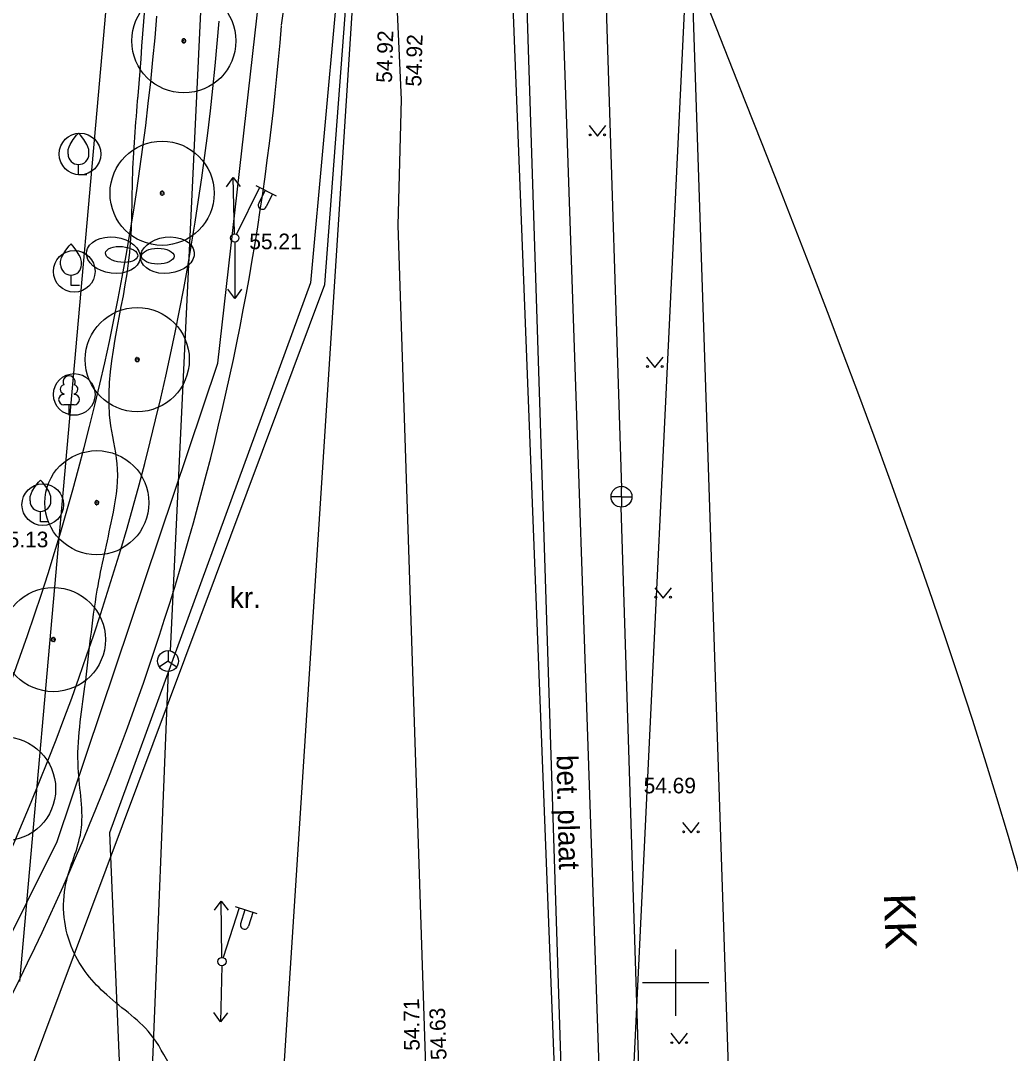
# Model space of a CAD drawing. Extents: x 9156 to 9809, y 2728 to 4000.
# Drawn here: x 9518.57 to 9566.07, y 3596.6 to 3646.17 of the extents above; entities that cross this region are included whole.
import ezdxf

# ---------------------------------------------------------------- set-up
doc = ezdxf.new("R2010")
doc.units = 0
for name, color, linetype in [('Level 1', 7, 'Continuous'), ('Level 16', 7, 'Continuous'), ('Level 17', 7, 'Continuous'), ('Level 18', 7, 'Continuous'), ('Level 21', 7, 'Continuous'), ('Level 54', 7, 'Continuous'), ('Level 56', 7, 'Continuous'), ('Level 58', 7, 'Continuous'), ('Level 7', 7, 'Continuous'), ('Level 8', 7, 'Continuous'), ('Level 9', 7, 'Continuous')]:
    doc.layers.add(name, color=color, linetype=linetype)

# ---------------------------------------------------------------- blocks, each defined once
blk = doc.blocks.new('KKOL')
at = {"layer": 'Level 58'}
for p, q in [((0, 1.59349), (0, -1.5935)), ((-1.5935, 0), (1.59349, 0))]:
    blk.add_line(p, q, dxfattribs=at)

msp = doc.modelspace()

# ---------------------------------------------------------------- linework, layer by layer
at = {"layer": 'Level 1'}
msp.add_line((9552.269, 3685.137), (9546.632, 3567.879), dxfattribs=at)
msp.add_line((9552.269, 3685.137), (9546.632, 3567.879), dxfattribs=at)
at = {"layer": 'Level 16'}
for p, q in [((9528.027, 3629.73), (9530.595, 3652.391)), ((9520.325, 3606.767), (9528.027, 3629.73)), ((9512.774, 3591.659), (9520.325, 3606.767))]:
    msp.add_line(p, q, dxfattribs=at)
at = {"layer": 'Level 17'}
msp.add_line((9531.089, 3645.951), (9534.27, 3668.117), dxfattribs=at)
for radius, start in [(123.6, 323.52136), (126.6, 332.03745)]:
    msp.add_arc((9404.886, 3655.965), radius, start, 355.44602, dxfattribs=at)
at = {"layer": 'Level 18'}
for p, q in [((9533.165, 3633.502), (9535.778, 3667.939)), ((9541.349, 3668.295), (9545.183, 3569.878)), ((9516.875, 3589.923), (9533.165, 3633.502))]:
    msp.add_line(p, q, dxfattribs=at)
msp.add_arc((9404.886, 3655.965), 120.6, 323.52136, 355.44602, dxfattribs=at)
at = {"layer": 'Level 21'}
for centre in [(9521.415, 3639.768), (9521.14, 3634.135), (9521.14, 3628.227), (9519.63, 3622.937)]:
    msp.add_circle(centre, 1, dxfattribs=at)
at = {"layer": 'Level 54'}
for p, q in [((9530.197, 3710.192), (9525.746, 3615.921)), ((9541.865, 3677.837), (9545.509, 3564.357)), ((9518.529, 3600.046), (9524.138, 3663.351)), ((9544.314, 3654.566), (9547.393, 3564.619)), ((9546.465, 3652.931), (9547.404, 3623.728)), ((9536.853, 3642.38), (9536.432, 3651.179)), ((9553.951, 3553.575), (9550.727, 3650.558)), ((9534.55, 3647.996), (9531.162, 3595.485)), ((9524.193, 3642.411), (9524.201, 3642.537)), ((9536.689, 3636.356), (9536.853, 3642.38)), ((9545.847, 3641.134), (9546.25, 3640.629)), ((9546.25, 3640.629), (9546.647, 3641.134)), ((9521.346, 3638.763), (9521.346, 3639.263)), ((9521.746, 3638.763), (9521.346, 3638.763)), ((9528.445, 3638.188), (9528.764, 3638.636)), ((9528.838, 3635.937), (9528.764, 3638.636)), ((9528.764, 3638.636), (9529.107, 3638.207)), ((9529.85, 3638.251), (9530.839, 3637.768)), ((9530.03, 3638.163), (9528.932, 3635.917)), ((9530.3, 3638.031), (9529.992, 3637.402)), ((9530.659, 3637.856), (9530.351, 3637.227)), ((9538.677, 3575.871), (9536.689, 3636.356)), ((9528.844, 3635.538), (9528.844, 3632.838)), ((9520.987, 3633.454), (9520.987, 3633.954)), ((9521.387, 3633.454), (9520.987, 3633.454)), ((9528.844, 3632.838), (9528.513, 3633.277)), ((9529.175, 3633.277), (9528.844, 3632.838)), ((9548.602, 3630.022), (9549.005, 3629.516)), ((9549.005, 3629.516), (9549.402, 3630.022)), ((9520.643, 3628.262), (9520.643, 3628.23)), ((9521.143, 3628.262), (9521.143, 3628.23)), ((9521.143, 3627.73), (9520.643, 3627.73)), ((9520.893, 3627.23), (9520.893, 3627.73)), ((9521.293, 3627.23), (9520.893, 3627.23)), ((9547.404, 3623.318), (9547.404, 3623.818)), ((9547.404, 3623.318), (9546.904, 3623.318)), ((9547.404, 3623.318), (9547.904, 3623.318)), ((9547.404, 3623.318), (9547.404, 3622.818)), ((9547.375, 3622.819), (9548.339, 3592.067)), ((9519.521, 3622.114), (9519.521, 3622.614)), ((9519.921, 3622.114), (9519.521, 3622.114)), ((9549.005, 3618.949), (9549.408, 3618.444)), ((9549.408, 3618.444), (9549.805, 3618.949)), ((9525.642, 3615.932), (9525.642, 3615.432)), ((9525.642, 3615.432), (9525.226, 3615.155)), ((9525.642, 3615.432), (9526.058, 3615.155)), ((9523.034, 3549.934), (9525.663, 3614.932)), ((9550.339, 3607.686), (9550.742, 3607.181)), ((9550.742, 3607.181), (9551.139, 3607.686)), ((9527.869, 3603.467), (9528.194, 3603.91)), ((9528.227, 3601.21), (9528.194, 3603.91)), ((9528.194, 3603.91), (9528.531, 3603.475)), ((9529.049, 3603.583), (9528.29, 3601.201)), ((9528.859, 3603.643), (9529.907, 3603.309)), ((9529.335, 3603.492), (9529.123, 3602.825)), ((9529.716, 3603.37), (9529.504, 3602.703)), ((9550, 3601.25), (9550, 3598.75)), ((9528.225, 3600.81), (9528.16, 3598.111)), ((9548.75, 3600), (9551.25, 3600)), ((9528.16, 3598.111), (9527.84, 3598.558)), ((9528.502, 3598.542), (9528.16, 3598.111)), ((9549.773, 3597.566), (9550.176, 3597.061)), ((9550.176, 3597.061), (9550.573, 3597.566))]:
    msp.add_line(p, q, dxfattribs=at)
for points in [[(9520.846, 3639.763), (9520.846, 3639.913), (9520.856, 3639.979), (9520.893, 3640.107), (9520.949, 3640.23), (9521.096, 3640.463), (9521.256, 3640.668), (9521.346, 3640.763)], [(9521.846, 3639.763), (9521.846, 3639.913), (9521.836, 3639.979), (9521.798, 3640.107), (9521.742, 3640.23), (9521.596, 3640.463), (9521.436, 3640.668), (9521.346, 3640.763)], [(9520.487, 3634.454), (9520.487, 3634.604), (9520.497, 3634.67), (9520.535, 3634.798), (9520.591, 3634.921), (9520.737, 3635.154), (9520.897, 3635.359), (9520.987, 3635.454)], [(9521.487, 3634.454), (9521.487, 3634.604), (9521.477, 3634.67), (9521.44, 3634.798), (9521.384, 3634.921), (9521.237, 3635.154), (9521.077, 3635.359), (9520.987, 3635.454)], [(9519.021, 3623.114), (9519.021, 3623.264), (9519.031, 3623.33), (9519.069, 3623.458), (9519.125, 3623.581), (9519.271, 3623.814), (9519.431, 3624.019), (9519.521, 3624.114)], [(9520.021, 3623.114), (9520.021, 3623.264), (9520.011, 3623.33), (9519.974, 3623.458), (9519.918, 3623.581), (9519.771, 3623.814), (9519.611, 3624.019), (9519.521, 3624.114)]]:
    msp.add_lwpolyline(points, dxfattribs=at)
for centre, radius in [((9545.897, 3640.684), 0.0428), ((9546.597, 3640.684), 0.0452), ((9528.844, 3635.738), 0.2), ((9548.652, 3629.572), 0.0428), ((9549.352, 3629.572), 0.0452), ((9547.404, 3623.318), 0.5), ((9549.055, 3618.499), 0.0428), ((9549.755, 3618.499), 0.0452), ((9525.642, 3615.432), 0.5), ((9550.389, 3607.236), 0.0428), ((9551.089, 3607.236), 0.0452), ((9528.23, 3601.01), 0.2), ((9549.823, 3597.116), 0.0428), ((9550.523, 3597.116), 0.0452)]:
    msp.add_circle(centre, radius, dxfattribs=at)
for centre, radius, start, end in [((9521.346, 3639.763), 0.5, 180, 0), ((9530.172, 3637.314), 0.2, 153.8818, 334.0032), ((9520.987, 3634.454), 0.5, 180, 0), ((9520.893, 3628.83), 0.292, 332.5799, 207.4201), ((9520.693, 3628.48), 0.224, 105.2441, 257.079), ((9521.093, 3628.48), 0.224, 282.921, 74.7559), ((9520.643, 3627.98), 0.25, 90, 270), ((9521.143, 3627.98), 0.25, 270, 90), ((9519.521, 3623.114), 0.5, 180, 0), ((9529.313, 3602.764), 0.2, 162.2685, 342.3899)]:
    msp.add_arc(centre, radius, start, end, dxfattribs=at)
for points in [[(9538.06, 3594.642), (9536.329, 3593.597), (9534.047, 3593.075), (9532.091, 3592.553), (9529.613, 3592.814), (9527.787, 3593.923), (9525.961, 3595.685), (9524.918, 3597.382), (9522.701, 3599.405), (9521.07, 3601.558), (9520.744, 3604.755), (9521.462, 3607.235), (9521.331, 3610.302), (9521.657, 3614.217), (9522.246, 3618.832), (9522.963, 3622.29), (9523.224, 3624.639), (9522.898, 3626.727), (9523.811, 3635.059), (9523.942, 3638.583), (9524.202, 3642.563), (9524.79, 3652.067), (9524.855, 3655.721), (9524.985, 3659.18), (9525.238, 3666.92)], [(9551.163, 3554.03), (9551.63, 3553.617), (9552.412, 3553.356), (9553.456, 3553.552), (9550.134, 3650.407)]]:
    msp.add_spline(points, degree=3, dxfattribs=at)
at = {"layer": 'Level 56'}
for p, q in [((9531.089, 3645.951), (9534.27, 3668.117)), ((9533.165, 3633.502), (9535.778, 3667.939)), ((9541.349, 3668.295), (9545.183, 3569.878)), ((9516.875, 3589.923), (9533.165, 3633.502))]:
    msp.add_line(p, q, dxfattribs=at)
for radius, start in [(120.6, 323.52136), (123.6, 323.52136), (126.6, 332.03745)]:
    msp.add_arc((9404.886, 3655.965), radius, start, 355.44602, dxfattribs=at)
at = {"layer": 'Level 7'}
for p, q in [((9535.382, 3665.696), (9532.485, 3633.588)), ((9532.485, 3633.588), (9522.84, 3607.185)), ((9522.84, 3607.185), (9527.159, 3503.746))]:
    msp.add_line(p, q, dxfattribs=at)
at = {"layer": 'Level 8'}
for centre, major_axis, ratio in [((9523.02, 3634.91), (1.285, -0.15), 0.674652), ((9523.02, 3634.91), (1.285, -0.15), 0.674652), ((9523.02, 3634.91), (1.285, -0.15), 0.674652), ((9523.02, 3634.91), (1.285, -0.15), 0.674652), ((9525.613, 3634.91), (-1.285, -0.15), 0.674652), ((9525.613, 3634.91), (-1.285, -0.15), 0.674652), ((9525.613, 3634.91), (-1.285, -0.15), 0.674652), ((9525.613, 3634.91), (-1.285, -0.15), 0.674652), ((9523.415, 3634.947), (0.774, -0.072), 0.486914), ((9523.415, 3634.947), (0.774, -0.072), 0.486914), ((9523.415, 3634.947), (0.774, -0.072), 0.486914), ((9523.415, 3634.947), (0.774, -0.072), 0.486914), ((9525.153, 3634.866), (-0.778, 0.002), 0.486914), ((9525.153, 3634.866), (-0.778, 0.002), 0.486914), ((9525.153, 3634.866), (-0.778, 0.002), 0.486914), ((9525.153, 3634.866), (-0.778, 0.002), 0.486914)]:
    msp.add_ellipse(centre, major_axis=major_axis, ratio=ratio, dxfattribs=at)
at = {"layer": 'Level 9'}
for p, q in [((9526.323, 3645.212), (9526.302, 3645.215)), ((9526.302, 3645.187), (9526.323, 3645.19)), ((9526.31, 3645.243), (9526.33, 3645.235)), ((9526.33, 3645.168), (9526.31, 3645.158)), ((9526.342, 3645.253), (9526.325, 3645.267)), ((9526.325, 3645.135), (9526.341, 3645.15)), ((9526.347, 3645.285), (9526.358, 3645.267)), ((9526.359, 3645.134), (9526.347, 3645.116)), ((9526.372, 3645.104), (9526.378, 3645.125)), ((9526.38, 3645.277), (9526.373, 3645.297)), ((9526.412, 3645.2), (9526.391, 3645.2)), ((9526.401, 3645.301), (9526.401, 3645.28)), ((9526.401, 3645.189), (9526.401, 3645.21)), ((9526.401, 3645.122), (9526.401, 3645.1)), ((9526.423, 3645.277), (9526.429, 3645.298)), ((9526.429, 3645.104), (9526.424, 3645.125)), ((9526.443, 3645.134), (9526.456, 3645.116)), ((9526.455, 3645.286), (9526.445, 3645.267)), ((9526.461, 3645.253), (9526.477, 3645.267)), ((9526.478, 3645.136), (9526.462, 3645.15)), ((9526.493, 3645.243), (9526.473, 3645.233)), ((9526.473, 3645.169), (9526.493, 3645.16)), ((9526.479, 3645.212), (9526.501, 3645.216)), ((9526.501, 3645.187), (9526.48, 3645.191)), ((9525.279, 3637.897), (9525.258, 3637.9)), ((9525.258, 3637.872), (9525.279, 3637.875)), ((9525.266, 3637.928), (9525.286, 3637.919)), ((9525.285, 3637.853), (9525.266, 3637.843)), ((9525.298, 3637.938), (9525.281, 3637.952)), ((9525.281, 3637.82), (9525.297, 3637.834)), ((9525.303, 3637.97), (9525.314, 3637.952)), ((9525.315, 3637.819), (9525.303, 3637.801)), ((9525.328, 3637.789), (9525.334, 3637.81)), ((9525.335, 3637.961), (9525.329, 3637.982)), ((9525.368, 3637.885), (9525.347, 3637.885)), ((9525.357, 3637.807), (9525.356, 3637.785)), ((9525.357, 3637.986), (9525.357, 3637.964)), ((9525.357, 3637.874), (9525.357, 3637.895)), ((9525.378, 3637.961), (9525.385, 3637.982)), ((9525.385, 3637.789), (9525.379, 3637.81)), ((9525.399, 3637.819), (9525.411, 3637.801)), ((9525.411, 3637.971), (9525.4, 3637.952)), ((9525.416, 3637.938), (9525.433, 3637.952)), ((9525.434, 3637.821), (9525.418, 3637.835)), ((9525.449, 3637.927), (9525.429, 3637.918)), ((9525.429, 3637.854), (9525.449, 3637.845)), ((9525.435, 3637.897), (9525.457, 3637.901)), ((9525.457, 3637.872), (9525.435, 3637.876)), ((9524.086, 3629.911), (9524.064, 3629.914)), ((9524.064, 3629.885), (9524.086, 3629.889)), ((9524.072, 3629.941), (9524.093, 3629.933)), ((9524.092, 3629.866), (9524.072, 3629.857)), ((9524.087, 3629.833), (9524.104, 3629.848)), ((9524.105, 3629.951), (9524.088, 3629.965)), ((9524.109, 3629.984), (9524.121, 3629.965)), ((9524.121, 3629.833), (9524.109, 3629.815)), ((9524.142, 3629.975), (9524.135, 3629.996)), ((9524.135, 3629.803), (9524.141, 3629.824)), ((9524.174, 3629.898), (9524.153, 3629.898)), ((9524.164, 3629.82), (9524.163, 3629.798)), ((9524.164, 3630), (9524.164, 3629.978)), ((9524.164, 3629.887), (9524.164, 3629.908)), ((9524.185, 3629.975), (9524.191, 3629.996)), ((9524.191, 3629.802), (9524.186, 3629.823)), ((9524.206, 3629.832), (9524.218, 3629.814)), ((9524.218, 3629.984), (9524.207, 3629.965)), ((9524.223, 3629.951), (9524.24, 3629.965)), ((9524.241, 3629.834), (9524.224, 3629.848)), ((9524.255, 3629.941), (9524.236, 3629.931)), ((9524.236, 3629.867), (9524.256, 3629.858)), ((9524.242, 3629.91), (9524.263, 3629.914)), ((9524.263, 3629.885), (9524.242, 3629.889)), ((9522.146, 3623.043), (9522.125, 3623.046)), ((9522.125, 3623.018), (9522.146, 3623.021)), ((9522.133, 3623.074), (9522.153, 3623.066)), ((9522.153, 3622.999), (9522.133, 3622.989)), ((9522.165, 3623.084), (9522.148, 3623.098)), ((9522.148, 3622.966), (9522.164, 3622.981)), ((9522.17, 3623.116), (9522.181, 3623.098)), ((9522.182, 3622.965), (9522.17, 3622.947)), ((9522.203, 3623.107), (9522.196, 3623.128)), ((9522.196, 3622.935), (9522.202, 3622.956)), ((9522.235, 3623.031), (9522.214, 3623.031)), ((9522.224, 3623.132), (9522.224, 3623.111)), ((9522.224, 3622.953), (9522.224, 3622.931)), ((9522.225, 3623.02), (9522.225, 3623.041)), ((9522.246, 3623.108), (9522.252, 3623.128)), ((9522.252, 3622.935), (9522.247, 3622.956)), ((9522.267, 3622.965), (9522.279, 3622.947)), ((9522.278, 3623.117), (9522.268, 3623.098)), ((9522.284, 3623.084), (9522.3, 3623.098)), ((9522.301, 3622.967), (9522.285, 3622.981)), ((9522.316, 3623.073), (9522.296, 3623.064)), ((9522.297, 3623), (9522.316, 3622.991)), ((9522.303, 3623.043), (9522.324, 3623.047)), ((9522.324, 3623.018), (9522.303, 3623.022)), ((9520.058, 3616.475), (9520.036, 3616.477)), ((9520.036, 3616.449), (9520.058, 3616.452)), ((9520.045, 3616.505), (9520.065, 3616.497)), ((9520.064, 3616.43), (9520.045, 3616.421)), ((9520.077, 3616.515), (9520.06, 3616.529)), ((9520.06, 3616.397), (9520.076, 3616.412)), ((9520.081, 3616.547), (9520.093, 3616.529)), ((9520.094, 3616.396), (9520.081, 3616.378)), ((9520.107, 3616.367), (9520.113, 3616.387)), ((9520.114, 3616.539), (9520.108, 3616.559)), ((9520.147, 3616.462), (9520.126, 3616.462)), ((9520.136, 3616.384), (9520.135, 3616.362)), ((9520.136, 3616.564), (9520.136, 3616.542)), ((9520.136, 3616.451), (9520.136, 3616.472)), ((9520.157, 3616.539), (9520.163, 3616.56)), ((9520.164, 3616.366), (9520.158, 3616.387)), ((9520.178, 3616.396), (9520.19, 3616.378)), ((9520.19, 3616.548), (9520.179, 3616.529)), ((9520.195, 3616.515), (9520.212, 3616.529)), ((9520.213, 3616.398), (9520.196, 3616.412)), ((9520.228, 3616.505), (9520.208, 3616.495)), ((9520.208, 3616.431), (9520.228, 3616.422)), ((9520.214, 3616.474), (9520.235, 3616.478)), ((9520.236, 3616.449), (9520.214, 3616.453))]:
    msp.add_line(p, q, dxfattribs=at)
for centre in [(9526.401, 3645.2), (9525.357, 3637.885), (9524.164, 3629.898), (9522.225, 3623.031), (9520.136, 3616.462), (9517.749, 3609.296)]:
    msp.add_circle(centre, 2.5, dxfattribs=at)
for centre, radius, start, end in [((9526.401, 3645.201), 0.101, 155.3123, 171.7042), ((9526.401, 3645.201), 0.101, 187.9671, 204.8625), ((9526.401, 3645.201), 0.0788, 171.5431, 187.6203), ((9526.401, 3645.201), 0.101, 122.8434, 139.0222), ((9526.401, 3645.201), 0.101, 220.7122, 237.1166), ((9526.401, 3645.201), 0.0788, 138.6432, 154.5795), ((9526.401, 3645.201), 0.0788, 204.4529, 220.4774), ((9526.401, 3645.201), 0.0788, 105.9559, 123.0564), ((9526.401, 3645.201), 0.0788, 237.451, 253.0843), ((9526.401, 3645.201), 0.101, 253.2952, 269.5718), ((9526.401, 3645.201), 0.101, 90.0356, 106.342), ((9526.401, 3645.201), 0.0788, 74.31, 90.043), ((9526.401, 3645.201), 0.0788, 269.9461, 286.3473), ((9526.401, 3645.201), 0.101, 57.6108, 74.1981), ((9526.401, 3645.201), 0.101, 285.972, 302.5562), ((9526.401, 3645.201), 0.0788, 302.254, 320.086), ((9526.401, 3645.201), 0.0788, 41.2062, 56.7795), ((9526.401, 3645.201), 0.0788, 8.0619, 24.0332), ((9526.401, 3645.201), 0.0788, 336.0557, 352.7558), ((9526.401, 3645.201), 0.101, 24.5394, 40.9852), ((9526.401, 3645.201), 0.101, 319.7777, 336.0738), ((9526.401, 3645.201), 0.101, 352.27, 8.583), ((9525.357, 3637.886), 0.101, 155.3123, 171.7042), ((9525.357, 3637.886), 0.101, 187.9671, 204.8625), ((9525.357, 3637.886), 0.0788, 171.5431, 187.6203), ((9525.357, 3637.886), 0.101, 122.8434, 139.0222), ((9525.357, 3637.886), 0.101, 220.7122, 237.1166), ((9525.357, 3637.886), 0.0788, 204.4529, 220.4774), ((9525.357, 3637.886), 0.0788, 138.6432, 154.5795), ((9525.357, 3637.886), 0.0788, 105.9559, 123.0564), ((9525.357, 3637.886), 0.0788, 237.451, 253.0843), ((9525.357, 3637.886), 0.101, 253.2952, 269.5718), ((9525.357, 3637.886), 0.101, 90.0356, 106.342), ((9525.357, 3637.886), 0.0788, 74.31, 90.043), ((9525.357, 3637.886), 0.0788, 269.9461, 286.3473), ((9525.357, 3637.886), 0.101, 57.6108, 74.1981), ((9525.357, 3637.886), 0.101, 285.972, 302.5562), ((9525.357, 3637.886), 0.0788, 302.254, 320.086), ((9525.357, 3637.886), 0.0788, 41.2062, 56.7795), ((9525.357, 3637.886), 0.0788, 8.0619, 24.0332), ((9525.357, 3637.886), 0.0788, 336.0557, 352.7558), ((9525.357, 3637.886), 0.101, 24.5394, 40.9852), ((9525.357, 3637.886), 0.101, 319.7777, 336.0738), ((9525.357, 3637.886), 0.101, 352.27, 8.583), ((9524.164, 3629.899), 0.101, 155.3123, 171.7042), ((9524.164, 3629.899), 0.101, 187.9671, 204.8625), ((9524.164, 3629.899), 0.0788, 171.5431, 187.6203), ((9524.164, 3629.899), 0.101, 220.7122, 237.1166), ((9524.164, 3629.899), 0.101, 122.8434, 139.0222), ((9524.164, 3629.899), 0.0788, 204.4529, 220.4774), ((9524.164, 3629.899), 0.0788, 138.6432, 154.5795), ((9524.164, 3629.899), 0.0788, 105.9559, 123.0564), ((9524.164, 3629.899), 0.0788, 237.451, 253.0843), ((9524.164, 3629.899), 0.101, 90.0356, 106.342), ((9524.164, 3629.899), 0.101, 253.2952, 269.5718), ((9524.164, 3629.899), 0.0788, 74.31, 90.043), ((9524.164, 3629.899), 0.0788, 269.9461, 286.3473), ((9524.164, 3629.899), 0.101, 57.6108, 74.1981), ((9524.164, 3629.899), 0.101, 285.972, 302.5562), ((9524.164, 3629.899), 0.0788, 302.254, 320.086), ((9524.164, 3629.899), 0.0788, 41.2062, 56.7795), ((9524.164, 3629.899), 0.0788, 8.0619, 24.0332), ((9524.164, 3629.899), 0.0788, 336.0557, 352.7558), ((9524.164, 3629.899), 0.101, 24.5394, 40.9852), ((9524.164, 3629.899), 0.101, 319.7777, 336.0738), ((9524.164, 3629.899), 0.101, 352.27, 8.583), ((9522.224, 3623.032), 0.101, 155.3123, 171.7042), ((9522.224, 3623.032), 0.101, 187.9671, 204.8625), ((9522.224, 3623.032), 0.0788, 171.5431, 187.6203), ((9522.224, 3623.032), 0.101, 220.7122, 237.1166), ((9522.224, 3623.032), 0.101, 122.8434, 139.0222), ((9522.224, 3623.032), 0.0788, 138.6432, 154.5795), ((9522.224, 3623.032), 0.0788, 204.4529, 220.4774), ((9522.224, 3623.032), 0.0788, 105.9559, 123.0564), ((9522.224, 3623.032), 0.0788, 237.451, 253.0843), ((9522.224, 3623.032), 0.101, 90.0356, 106.342), ((9522.224, 3623.032), 0.101, 253.2952, 269.5718), ((9522.224, 3623.032), 0.0788, 74.31, 90.043), ((9522.224, 3623.032), 0.0788, 269.9461, 286.3473), ((9522.224, 3623.032), 0.101, 57.6108, 74.1981), ((9522.224, 3623.032), 0.101, 285.972, 302.5562), ((9522.224, 3623.032), 0.0788, 302.254, 320.086), ((9522.224, 3623.032), 0.0788, 41.2062, 56.7795), ((9522.224, 3623.032), 0.0788, 8.0619, 24.0332), ((9522.224, 3623.032), 0.0788, 336.0557, 352.7558), ((9522.224, 3623.032), 0.101, 24.5394, 40.9852), ((9522.224, 3623.032), 0.101, 319.7777, 336.0738), ((9522.224, 3623.032), 0.101, 352.27, 8.583), ((9520.136, 3616.463), 0.101, 155.3123, 171.7042), ((9520.136, 3616.463), 0.101, 187.9671, 204.8625), ((9520.136, 3616.463), 0.0788, 171.5431, 187.6203), ((9520.136, 3616.463), 0.101, 122.8434, 139.0222), ((9520.136, 3616.463), 0.101, 220.7122, 237.1166), ((9520.136, 3616.463), 0.0788, 204.4529, 220.4774), ((9520.136, 3616.463), 0.0788, 138.6432, 154.5795), ((9520.136, 3616.463), 0.0788, 105.9559, 123.0564), ((9520.136, 3616.463), 0.0788, 237.451, 253.0843), ((9520.136, 3616.463), 0.101, 253.2952, 269.5718), ((9520.136, 3616.463), 0.101, 90.0356, 106.342), ((9520.136, 3616.463), 0.0788, 74.31, 90.043), ((9520.136, 3616.463), 0.0788, 269.9461, 286.3473), ((9520.136, 3616.463), 0.101, 57.6108, 74.1981), ((9520.136, 3616.463), 0.101, 285.972, 302.5562), ((9520.136, 3616.463), 0.0788, 302.254, 320.086), ((9520.136, 3616.463), 0.0788, 41.2062, 56.7795), ((9520.136, 3616.463), 0.0788, 8.0619, 24.0332), ((9520.136, 3616.463), 0.0788, 336.0557, 352.7558), ((9520.136, 3616.463), 0.101, 24.5394, 40.9852), ((9520.136, 3616.463), 0.101, 319.7777, 336.0738), ((9520.136, 3616.463), 0.101, 352.27, 8.583)]:
    msp.add_arc(centre, radius, start, end, dxfattribs=at)

# ---------------------------------------------------------------- block references
at = {"layer": 'Level 54'}
msp.add_blockref('KKOL', (9550, 3600), dxfattribs=at)

# ---------------------------------------------------------------- texts
for s, height, rotation, p in [('54.92', 0.75, 88.4462, (9536.387, 3643.177)), ('54.92', 0.75, 88.4462, (9537.795, 3642.997)), ('kr.', 1, 359.8403, (9528.608, 3617.979)), ('bet. plaat', 1, 271.2586, (9544.287, 3610.913)), ('KK', 1.5, 271.9045, (9559.994, 3604.252)), ('54.71', 0.75, 90.6359, (9537.72, 3596.732)), ('54.63', 0.75, 91.8821, (9539.01, 3596.294))]:
    msp.add_text(s, height=height, rotation=rotation, dxfattribs=at).set_placement(p)
for s, p in [('55.21', (9529.544, 3635.197)), ('55.13', (9517.388, 3620.892)), ('54.69', (9548.468, 3609.082))]:
    msp.add_text(s, height=0.75, dxfattribs=at).set_placement(p)

doc.saveas('drawing.dxf')
